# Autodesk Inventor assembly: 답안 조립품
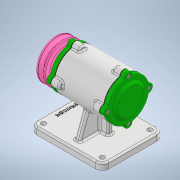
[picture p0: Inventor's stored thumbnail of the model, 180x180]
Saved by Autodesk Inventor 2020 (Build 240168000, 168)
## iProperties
Created: 2022-11
Part Number: 답안 조립품
Document SubType Name: Assembly
Designer: owner
Author: owner
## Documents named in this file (12)
- C:\Users\owner\Desktop\721108V1022\답안 조립품.iam
- C:\Users\owner\Desktop\721108V1022\본체.ipt
- C:\Users\owner\Desktop\721108V1022\V-벨트풀리.ipt
- C:\Users\owner\Desktop\721108V1022\개스킷.ipt
- C:\Users\owner\Desktop\721108V1022\너트 M12 x 1.25.ipt
- C:\Users\owner\Desktop\721108V1022\뒤커버.ipt
- C:\Users\owner\Desktop\721108V1022\베어링 6204.ipt
- C:\Users\owner\Desktop\721108V1022\볼트 M4 x 12.ipt
- C:\Users\owner\Desktop\721108V1022\앞커버.ipt
- C:\Users\owner\Desktop\721108V1022\오일 실.ipt
- C:\Users\owner\Desktop\721108V1022\축.ipt
- C:\Users\owner\Desktop\721108V1022\키 4 x 4.ipt
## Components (8 placed, 6 different names)
1. V-벨트풀리:1 — 각도:1
2. 개스킷:1
3. KS B 1012 클래스 1 일반 - 미터 M12x1.25:1 — 각도:1
4. KS B 2023 6204 - 20 x 47 x 14:1
5. KS B 2804 D D - 20 32 8:1
6. KS B 1311 (I) 4 x 4 x 12:1
7. KS B 2023 6204 - 20 x 47 x 14:2
8. 개스킷:2
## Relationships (1: Angle 1)
- 각도:1 [Angle]: V-벨트풀리:1 ↔ KS B 1012 클래스 1 일반 - 미터 M12x1.25:1
